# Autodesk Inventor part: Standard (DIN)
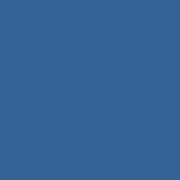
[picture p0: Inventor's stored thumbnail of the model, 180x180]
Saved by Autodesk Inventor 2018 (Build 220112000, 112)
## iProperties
Shininess: 64.0
Length Units: 11269
Angle Units: 11279
Time Units: 11290
Mass Units: 11283
Length Display Precision: 3
Angle Display Precision: 2
Compacted: True
Part Number: Standard (DIN)
Document SubType Name: Modeling
Created: 2002-07
Density: 1 g/cm^3
Material: Generic
Appearance: Default
Density: 0.0
Volumn: 0.0
Area: 0.0
PropertySet Name: Model Information
Control State: 0
Master: False
Checked Out: False
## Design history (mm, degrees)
node "Volumenkörper1"
